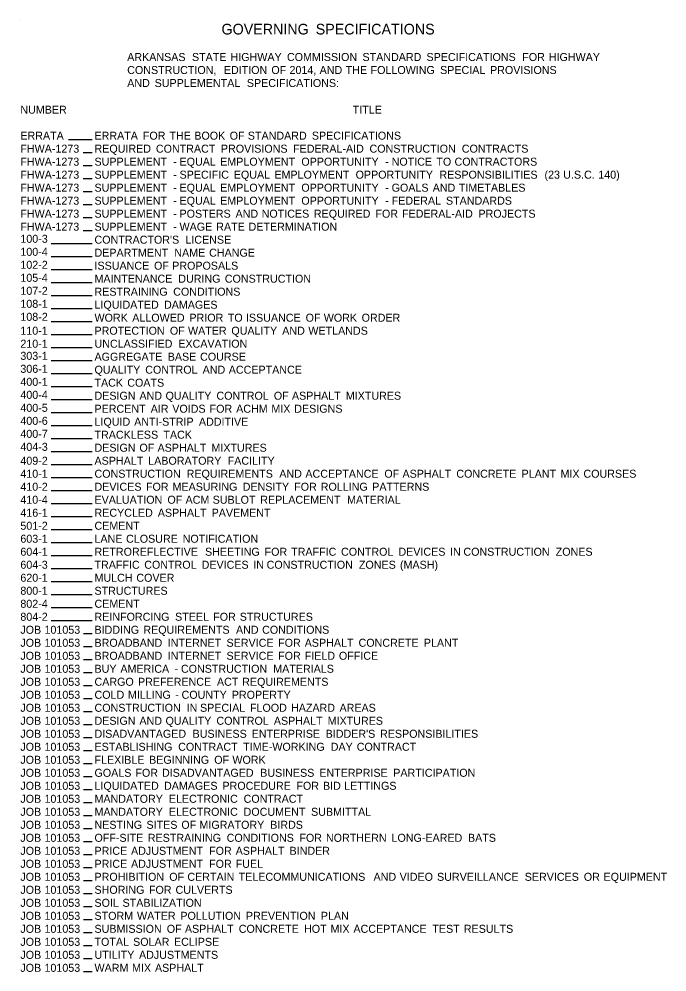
# Model space of a CAD drawing. Extents: x 194 to 1654, y 38 to 1017.
# Drawn here: x 194 to 777, y 126 to 983 of the extents above; entities that cross this region are included whole.
import ezdxf

# ---------------------------------------------------------------- set-up
doc = ezdxf.new("R2010")
doc.units = 0
for name, color, linetype in [('Default', 7, 'Continuous'), ('R_Draft', 7, 'Continuous'), ('R_No Plot', 7, 'Continuous')]:
    doc.layers.add(name, color=color, linetype=linetype)

msp = doc.modelspace()

# ---------------------------------------------------------------- linework, layer by layer
at = {"layer": 'R_Draft'}
for p, q in [((259.88, 874.64), (238.72, 874.64)), ((259.88, 862.94), (251.86, 862.94)), ((259.88, 851.24), (251.86, 851.24)), ((259.88, 839.54), (251.86, 839.54)), ((259.88, 827.84), (251.86, 827.84)), ((259.88, 816.14), (251.86, 816.14)), ((259.88, 804.44), (251.86, 804.44)), ((259.88, 792.74), (251.86, 792.74)), ((259.88, 781.04), (223.07, 781.04)), ((259.88, 769.34), (223.07, 769.34)), ((259.88, 757.64), (223.07, 757.64)), ((259.88, 745.94), (223.07, 745.94)), ((259.88, 734.24), (223.07, 734.24)), ((259.88, 722.54), (223.07, 722.54)), ((259.88, 710.84), (223.07, 710.84)), ((259.88, 699.14), (223.07, 699.14)), ((259.88, 687.44), (223.07, 687.44)), ((259.88, 675.74), (223.07, 675.74)), ((259.88, 664.04), (223.07, 664.04)), ((259.88, 652.34), (223.07, 652.34)), ((259.88, 640.64), (223.07, 640.64)), ((259.88, 628.94), (223.07, 628.94)), ((259.88, 617.24), (223.07, 617.24)), ((259.88, 605.54), (223.07, 605.54)), ((259.88, 593.84), (223.07, 593.84)), ((259.88, 582.14), (223.07, 582.14)), ((259.88, 570.44), (223.07, 570.44)), ((259.88, 558.74), (223.07, 558.74)), ((259.88, 547.04), (223.07, 547.04)), ((259.88, 535.34), (223.07, 535.34)), ((259.88, 523.64), (223.07, 523.64)), ((259.88, 511.94), (223.07, 511.94)), ((259.88, 500.24), (223.07, 500.24)), ((259.88, 488.54), (223.07, 488.54)), ((259.88, 476.84), (223.07, 476.84)), ((259.88, 465.14), (223.07, 465.14)), ((259.88, 453.44), (223.07, 453.44)), ((259.88, 441.74), (223.07, 441.74)), ((259.88, 430.04), (252.22, 430.04)), ((259.88, 418.34), (252.22, 418.34)), ((259.88, 406.64), (252.22, 406.64)), ((259.88, 394.94), (252.22, 394.94)), ((259.88, 383.24), (252.22, 383.24)), ((259.88, 371.54), (252.22, 371.54)), ((259.88, 359.84), (252.22, 359.84)), ((259.88, 348.14), (252.22, 348.14)), ((259.88, 336.44), (252.22, 336.44)), ((259.88, 324.74), (252.22, 324.74)), ((259.88, 313.04), (252.22, 313.04)), ((259.88, 301.34), (252.22, 301.34)), ((259.88, 289.64), (252.22, 289.64)), ((259.88, 277.94), (252.22, 277.94)), ((259.88, 266.24), (252.22, 266.24)), ((259.88, 254.54), (252.22, 254.54)), ((259.88, 242.84), (252.22, 242.84)), ((259.88, 231.14), (252.22, 231.14)), ((259.88, 219.44), (252.22, 219.44)), ((259.88, 207.74), (252.22, 207.74)), ((259.88, 196.04), (252.22, 196.04)), ((259.88, 184.34), (252.22, 184.34)), ((259.88, 172.64), (252.22, 172.64)), ((259.88, 160.94), (252.22, 160.94)), ((259.88, 149.24), (252.22, 149.24)), ((259.88, 137.54), (252.22, 137.54)), ((259.88, 125.84), (252.22, 125.84))]:
    msp.add_line(p, q, dxfattribs=at)
at = {"layer": 'R_No Plot'}
msp.add_line((194.13, 983.18), (194.13, 983.18), dxfattribs=at)

# ---------------------------------------------------------------- texts
at = {"layer": 'Default'}
for s, height, p in [('GOVERNING', 9.6, (376.25, 969.3)), (' SPECIFICATIONS', 9.6, (457.42, 969.3)), ('           ARKANSAS', 7.2, (261.99, 945.42)), (' STATE', 7.2, (346.99, 945.42)), (' HIGHWAY', 7.2, (381.68, 945.42)), (' COMMISSION', 7.2, (432.46, 945.42)), (' STANDARD', 7.2, (500.38, 945.42)), (' SPECIFICATIONS', 7.2, (557.98, 945.42)), (' FOR', 7.2, (644.1, 945.42)), (' HIGHWAY', 7.2, (668, 945.42)), ('           CONSTRUCTION,', 7.2, (261.99, 933.72)), (' EDITION', 7.2, (375.66, 933.72)), (' OF', 7.2, (418.43, 933.72)), (' 2014,', 7.2, (434.74, 933.72)), (' AND', 7.2, (461.8, 933.72)), (' THE', 7.2, (485.3, 933.72)), (' FOLLOWING', 7.2, (507.68, 933.72)), (' SPECIAL', 7.2, (570.2, 933.72)), (' PROVISIONS', 7.2, (615.13, 933.72)), ('           AND', 7.2, (261.99, 922.02)), (' SUPPLEMENTAL', 7.2, (313.42, 922.02)), (' SPECIFICATIONS:', 7.2, (396.37, 922.02)), ('NUMBER', 7.2, (195.3, 898.04)), ('TITLE', 7.2, (494.26, 898.04)), ('ERRATA', 7.2, (195.3, 874.64)), ('ERRATA', 7.2, (261.99, 874.64)), (' FOR', 7.2, (302.82, 874.64)), (' THE', 7.2, (326.71, 874.64)), (' BOOK', 7.2, (349.09, 874.64)), (' OF', 7.2, (380.94, 874.64)), (' STANDARD', 7.2, (397.24, 874.64)), (' SPECIFICATIONS', 7.2, (454.84, 874.64)), ('FHWA-1273', 7.2, (195.3, 862.94)), ('REQUIRED', 7.2, (261.99, 862.94)), (' CONTRACT', 7.2, (314.56, 862.94)), (' PROVISIONS', 7.2, (373.04, 862.94)), (' FEDERAL-AID', 7.2, (437.93, 862.94)), (' CONSTRUCTION', 7.2, (506.7, 862.94)), (' CONTRACTS', 7.2, (589.72, 862.94)), ('FHWA-1273', 7.2, (195.3, 851.24)), ('SUPPLEMENT', 7.2, (261.99, 851.24)), (' EQUAL', 7.2, (335.82, 851.24)), (' EMPLOYMENT', 7.2, (372.37, 851.24)), (' OPPORTUNITY', 7.2, (445.39, 851.24)), (' NOTICE', 7.2, (526.61, 851.24)), (' TO', 7.2, (566.87, 851.24)), (' CONTRACTORS', 7.2, (583.19, 851.24)), (' -', 7.2, (330, 851.24)), (' -', 7.2, (520.78, 851.24)), ('FHWA-1273', 7.2, (195.3, 839.54)), ('SUPPLEMENT', 7.2, (261.99, 839.54)), (' -', 7.2, (330, 839.54)), (' SPECIFIC', 7.2, (335.82, 839.54)), (' EQUAL', 7.2, (384.62, 839.54)), (' EMPLOYMENT', 7.2, (421.16, 839.54)), (' OPPORTUNITY', 7.2, (494.19, 839.54)), (' RESPONSIBILITIES', 7.2, (569.57, 839.54)), (' (23', 7.2, (664.09, 839.54)), (' U.S.C.', 7.2, (680.96, 839.54)), (' 140)', 7.2, (712.5, 839.54)), ('FHWA-1273', 7.2, (195.3, 827.84)), ('SUPPLEMENT', 7.2, (261.99, 827.84)), (' EQUAL', 7.2, (335.82, 827.84)), (' EMPLOYMENT', 7.2, (372.37, 827.84)), (' OPPORTUNITY', 7.2, (445.39, 827.84)), (' GOALS', 7.2, (526.61, 827.84)), (' AND', 7.2, (563.54, 827.84)), (' TIMETABLES', 7.2, (587.04, 827.84)), ('FHWA-1273', 7.2, (195.3, 816.14)), ('SUPPLEMENT', 7.2, (261.99, 816.14)), (' -', 7.2, (330, 827.84)), (' EQUAL', 7.2, (335.82, 816.14)), (' EMPLOYMENT', 7.2, (372.37, 816.14)), (' OPPORTUNITY', 7.2, (445.39, 816.14)), (' -', 7.2, (520.78, 827.84)), (' FEDERAL', 7.2, (526.61, 816.14)), (' STANDARDS', 7.2, (575.45, 816.14)), (' -', 7.2, (330, 816.14)), (' -', 7.2, (520.78, 816.14)), ('FHWA-1273', 7.2, (195.3, 804.44)), ('SUPPLEMENT', 7.2, (261.99, 804.44)), (' -', 7.2, (330, 804.44)), (' POSTERS', 7.2, (335.82, 804.44)), (' AND', 7.2, (386.18, 804.44)), (' NOTICES', 7.2, (409.67, 804.44)), (' REQUIRED', 7.2, (456.66, 804.44)), (' FOR', 7.2, (512.02, 804.44)), (' FEDERAL-AID', 7.2, (535.92, 804.44)), (' PROJECTS', 7.2, (604.69, 804.44)), ('FHWA-1273', 7.2, (195.3, 792.74)), ('SUPPLEMENT', 7.2, (261.99, 792.74)), (' WAGE', 7.2, (335.82, 792.74)), (' RATE', 7.2, (368.82, 792.74)), (' DETERMINATION', 7.2, (397.91, 792.74)), ('100-3', 7.2, (195.3, 781.85)), (' -', 7.2, (330, 792.74)), ("CONTRACTOR'S", 7.2, (261.99, 781.04)), (' LICENSE', 7.2, (341.08, 781.04)), ('100-4', 7.2, (195.3, 770.15)), ('DEPARTMENT', 7.2, (261.99, 769.34)), (' NAME', 7.2, (331.1, 769.34)), (' CHANGE', 7.2, (362.43, 769.34)), ('102-2', 7.2, (195.3, 758.45)), ('ISSUANCE', 7.2, (261.99, 757.64)), (' OF', 7.2, (312.89, 757.64)), (' PROPOSALS', 7.2, (329.2, 757.64)), ('105-4', 7.2, (195.3, 746.75)), ('MAINTENANCE', 7.2, (261.99, 745.94)), (' DURING', 7.2, (334.68, 745.94)), (' CONSTRUCTION', 7.2, (376.53, 745.94)), ('107-2', 7.2, (195.3, 735.05)), ('RESTRAINING', 7.2, (261.99, 734.24)), (' CONDITIONS', 7.2, (330.12, 734.24)), ('108-1', 7.2, (195.3, 723.35)), ('LIQUIDATED', 7.2, (261.99, 722.54)), (' DAMAGES', 7.2, (321.83, 722.54)), ('108-2', 7.2, (195.3, 711.65)), ('WORK', 7.2, (261.99, 710.84)), (' ALLOWED', 7.2, (293.27, 710.84)), (' PRIOR', 7.2, (344.71, 710.84)), (' TO', 7.2, (379.23, 710.84)), (' ISSUANCE', 7.2, (395.55, 710.84)), (' OF', 7.2, (449.24, 710.84)), (' WORK', 7.2, (465.55, 710.84)), (' ORDER', 7.2, (499.61, 710.84)), ('110-1', 7.2, (195.3, 699.14)), ('PROTECTION', 7.2, (261.99, 699.14)), (' OF', 7.2, (327.13, 699.14)), (' WATER', 7.2, (343.43, 699.14)), (' QUALITY', 7.2, (382.42, 699.14)), (' AND', 7.2, (428.18, 699.14)), (' WETLANDS', 7.2, (451.68, 699.14)), ('210-1', 7.2, (195.3, 687.44)), ('UNCLASSIFIED', 7.2, (261.99, 687.44)), (' EXCAVATION', 7.2, (334.69, 687.44)), ('303-1', 7.2, (195.3, 676.55)), ('AGGREGATE', 7.2, (261.99, 675.74)), (' BASE', 7.2, (325.19, 675.74)), (' COURSE', 7.2, (354.29, 675.74)), ('306-1', 7.2, (195.3, 664.85)), ('QUALITY', 7.2, (261.99, 664.04)), (' CONTROL', 7.2, (304.96, 664.04)), (' AND', 7.2, (356.58, 664.04)), (' ACCEPTANCE', 7.2, (380.08, 664.04)), ('400-1', 7.2, (195.3, 653.15)), ('TACK', 7.2, (261.99, 652.34)), (' COATS', 7.2, (288.8, 652.34)), ('400-4', 7.2, (195.3, 641.45)), ('DESIGN', 7.2, (261.99, 640.64)), (' AND', 7.2, (299.74, 640.64)), (' QUALITY', 7.2, (323.24, 640.64)), (' CONTROL', 7.2, (369, 640.64)), (' OF', 7.2, (420.63, 640.64)), (' ASPHALT', 7.2, (436.93, 640.64)), (' MIXTURES', 7.2, (485.37, 640.64)), ('400-5', 7.2, (195.3, 629.75)), ('PERCENT', 7.2, (261.99, 628.94)), (' AIR', 7.2, (309.87, 628.94)), (' VOIDS', 7.2, (329.29, 628.94)), (' FOR', 7.2, (362.87, 628.94)), (' ACHM', 7.2, (386.76, 628.94)), (' MIX', 7.2, (418.42, 628.94)), (' DESIGNS', 7.2, (439.03, 628.94)), ('400-6', 7.2, (195.3, 618.05)), ('LIQUID', 7.2, (261.99, 617.24)), (' ANTI-STRIP', 7.2, (294.99, 617.24)), (' ADDITIVE', 7.2, (353.24, 617.24)), ('400-7', 7.2, (195.3, 606.35)), ('TRACKLESS', 7.2, (261.99, 605.54)), (' TACK', 7.2, (321.29, 605.54)), ('404-3', 7.2, (195.3, 594.65)), ('DESIGN', 7.2, (261.99, 593.84)), (' OF', 7.2, (299.74, 593.84)), (' ASPHALT', 7.2, (316.05, 593.84)), (' MIXTURES', 7.2, (364.49, 593.84)), ('409-2', 7.2, (195.3, 582.14)), ('ASPHALT', 7.2, (261.99, 582.14)), (' LABORATORY', 7.2, (307.64, 582.14)), (' FACILITY', 7.2, (379.12, 582.14)), ('410-1', 7.2, (195.3, 570.44)), ('CONSTRUCTION', 7.2, (261.99, 570.44)), (' REQUIREMENTS', 7.2, (342.21, 570.44)), (' AND', 7.2, (425.53, 570.44)), (' ACCEPTANCE', 7.2, (449.03, 570.44)), (' OF', 7.2, (520.06, 570.44)), (' ASPHALT', 7.2, (536.36, 570.44)), (' CONCRETE', 7.2, (584.8, 570.44)), (' PLANT', 7.2, (643.51, 570.44)), (' MIX', 7.2, (678.53, 570.44)), (' COURSES', 7.2, (699.14, 570.44)), ('410-2', 7.2, (195.3, 558.74)), ('DEVICES', 7.2, (261.99, 558.74)), (' FOR', 7.2, (305.64, 558.74)), (' MEASURING', 7.2, (329.53, 558.74)), (' DENSITY', 7.2, (392.62, 558.74)), (' FOR', 7.2, (438.95, 558.74)), (' ROLLING', 7.2, (462.84, 558.74)), (' PATTERNS', 7.2, (509.16, 558.74)), ('410-4', 7.2, (195.3, 547.04)), ('EVALUATION', 7.2, (261.99, 547.04)), (' OF', 7.2, (324.9, 547.04)), (' ACM', 7.2, (341.21, 547.04)), (' SUBLOT', 7.2, (365.6, 547.04)), (' REPLACEMENT', 7.2, (408.44, 547.04)), (' MATERIAL', 7.2, (486.51, 547.04)), ('416-1', 7.2, (195.3, 535.34)), ('RECYCLED', 7.2, (261.99, 535.34)), (' ASPHALT', 7.2, (316.24, 535.34)), (' PAVEMENT', 7.2, (364.68, 535.34)), ('501-2', 7.2, (195.3, 523.64)), ('CEMENT', 7.2, (261.99, 523.64)), ('603-1', 7.2, (195.3, 511.94)), ('LANE', 7.2, (261.99, 511.94)), (' CLOSURE', 7.2, (287.73, 511.94)), (' NOTIFICATION', 7.2, (338.63, 511.94)), ('604-1', 7.2, (195.3, 500.24)), ('RETROREFLECTIVE', 7.2, (261.99, 500.24)), (' SHEETING', 7.2, (358.73, 500.24)), (' FOR', 7.2, (412.32, 500.24)), (' TRAFFIC', 7.2, (436.21, 500.24)), (' CONTROL', 7.2, (481.08, 500.24)), (' DEVICES', 7.2, (532.7, 500.24)), (' IN', 7.2, (579.14, 500.24)), (' CONSTRUCTION', 7.2, (591.17, 500.24)), (' ZONES', 7.2, (674.19, 500.24)), ('604-3', 7.2, (195.3, 488.54)), ('TRAFFIC', 7.2, (261.99, 488.54)), (' CONTROL', 7.2, (304.07, 488.54)), (' DEVICES', 7.2, (355.69, 488.54)), (' IN', 7.2, (402.13, 488.54)), (' CONSTRUCTION', 7.2, (414.16, 488.54)), (' ZONES', 7.2, (497.17, 488.54)), (' (MASH)', 7.2, (534.1, 488.54)), ('620-1', 7.2, (195.3, 476.84)), ('MULCH', 7.2, (261.99, 476.84)), (' COVER', 7.2, (296.95, 476.84)), ('800-1', 7.2, (195.3, 465.14)), ('STRUCTURES', 7.2, (261.99, 465.14)), ('802-4', 7.2, (195.3, 453.44)), ('CEMENT', 7.2, (261.99, 453.44)), ('804-2', 7.2, (195.3, 441.74)), ('REINFORCING', 7.2, (261.99, 441.74)), (' STEEL', 7.2, (331.79, 441.74)), (' FOR', 7.2, (366.1, 441.74)), (' STRUCTURES', 7.2, (389.99, 441.74)), ('JOB', 7.2, (195.3, 430.04)), (' 101053', 7.2, (214.33, 430.04)), ('BIDDING', 7.2, (261.99, 430.04)), (' REQUIREMENTS', 7.2, (303.28, 430.04)), (' CONDITIONS', 7.2, (410.1, 430.04)), (' AND', 7.2, (386.6, 430.04)), ('JOB', 7.2, (195.3, 418.34)), (' 101053', 7.2, (214.33, 418.34)), ('BROADBAND', 7.2, (261.99, 418.34)), (' INTERNET', 7.2, (325.19, 418.34)), (' SERVICE', 7.2, (378.09, 418.34)), (' FOR', 7.2, (424.51, 418.34)), (' ASPHALT', 7.2, (448.41, 418.34)), (' CONCRETE', 7.2, (496.85, 418.34)), (' PLANT', 7.2, (555.56, 418.34)), ('JOB', 7.2, (195.3, 406.64)), (' 101053', 7.2, (214.33, 406.64)), ('BROADBAND', 7.2, (261.99, 406.64)), (' INTERNET', 7.2, (325.19, 406.64)), (' SERVICE', 7.2, (378.09, 406.64)), (' FOR', 7.2, (424.51, 406.64)), (' FIELD', 7.2, (448.41, 406.64)), (' OFFICE', 7.2, (479.17, 406.64)), ('JOB', 7.2, (195.3, 394.94)), (' 101053', 7.2, (214.33, 394.94)), ('BUY', 7.2, (261.99, 394.94)), (' AMERICA', 7.2, (282.6, 394.94)), (' -', 7.2, (331.25, 394.94)), (' CONSTRUCTION', 7.2, (337.08, 394.94)), (' MATERIALS', 7.2, (420.1, 394.94)), ('JOB', 7.2, (195.3, 383.24)), (' 101053', 7.2, (214.33, 383.24)), ('CARGO', 7.2, (261.99, 383.24)), (' PREFERENCE', 7.2, (298.44, 383.24)), (' ACT', 7.2, (369.46, 383.24)), (' REQUIREMENTS', 7.2, (392.17, 383.24)), ('JOB', 7.2, (195.3, 371.54)), (' 101053', 7.2, (214.33, 371.54)), ('COLD', 7.2, (261.99, 371.54)), (' MILLING', 7.2, (289.4, 371.54)), (' COUNTY', 7.2, (337.64, 371.54)), (' PROPERTY', 7.2, (382.83, 371.54)), (' -', 7.2, (331.81, 371.54)), ('JOB', 7.2, (195.3, 359.84)), (' 101053', 7.2, (214.33, 359.84)), ('CONSTRUCTION', 7.2, (261.99, 359.84)), (' IN', 7.2, (342.21, 359.84)), (' SPECIAL', 7.2, (354.24, 359.84)), (' FLOOD', 7.2, (399.18, 359.84)), (' HAZARD', 7.2, (436.09, 359.84)), (' AREAS', 7.2, (479.71, 359.84)), ('JOB', 7.2, (195.3, 348.14)), (' 101053', 7.2, (214.33, 348.14)), ('DESIGN', 7.2, (261.99, 348.14)), (' AND', 7.2, (299.74, 348.14)), (' QUALITY', 7.2, (323.24, 348.14)), (' CONTROL', 7.2, (369, 348.14)), (' ASPHALT', 7.2, (420.63, 348.14)), (' MIXTURES', 7.2, (469.07, 348.14)), ('JOB', 7.2, (195.3, 336.44)), (' 101053', 7.2, (214.33, 336.44)), ('DISADVANTAGED', 7.2, (261.99, 336.44)), (' BUSINESS', 7.2, (347.55, 336.44)), (' ENTERPRISE', 7.2, (400.7, 336.44)), (" BIDDER'S", 7.2, (467.25, 336.44)), (' RESPONSIBILITIES', 7.2, (516.16, 336.44)), ('JOB', 7.2, (195.3, 324.74)), (' 101053', 7.2, (214.33, 324.74)), ('ESTABLISHING', 7.2, (261.99, 324.74)), (' CONTRACT', 7.2, (334.6, 324.74)), (' TIME-WORKING', 7.2, (393.08, 324.74)), (' DAY', 7.2, (471.81, 324.74)), (' CONTRACT', 7.2, (495.21, 324.74)), ('JOB', 7.2, (195.3, 313.04)), (' 101053', 7.2, (214.33, 313.04)), ('FLEXIBLE', 7.2, (261.99, 313.04)), (' BEGINNING', 7.2, (308.42, 313.04)), (' OF', 7.2, (367.04, 313.04)), (' WORK', 7.2, (383.35, 313.04)), ('JOB', 7.2, (195.3, 301.34)), (' 101053', 7.2, (214.33, 301.34)), ('GOALS', 7.2, (261.99, 301.34)), (' FOR', 7.2, (296.13, 301.34)), (' DISADVANTAGED', 7.2, (320.03, 301.34)), (' BUSINESS', 7.2, (408.38, 301.34)), (' ENTERPRISE', 7.2, (461.53, 301.34)), (' PARTICIPATION', 7.2, (528.08, 301.34)), ('JOB', 7.2, (195.3, 289.64)), (' 101053', 7.2, (214.33, 289.64)), ('LIQUIDATED', 7.2, (261.99, 289.64)), (' DAMAGES', 7.2, (321.83, 289.64)), (' PROCEDURE', 7.2, (374.41, 289.64)), (' FOR', 7.2, (440.95, 289.64)), (' BID', 7.2, (464.85, 289.64)), (' LETTINGS', 7.2, (483.87, 289.64)), ('JOB', 7.2, (195.3, 277.94)), (' 101053', 7.2, (214.33, 277.94)), ('MANDATORY', 7.2, (261.99, 277.94)), (' ELECTRONIC', 7.2, (326.2, 277.94)), (' CONTRACT', 7.2, (393.44, 277.94)), ('JOB', 7.2, (195.3, 266.24)), (' 101053', 7.2, (214.33, 266.24)), ('MANDATORY', 7.2, (261.99, 266.24)), (' ELECTRONIC', 7.2, (326.2, 266.24)), (' DOCUMENT', 7.2, (393.44, 266.24)), (' SUBMITTAL', 7.2, (454.15, 266.24)), ('JOB', 7.2, (195.3, 254.54)), (' 101053', 7.2, (214.33, 254.54)), ('NESTING', 7.2, (261.99, 254.54)), (' SITES', 7.2, (306.08, 254.54)), (' OF', 7.2, (337.42, 254.54)), (' MIGRATORY', 7.2, (353.73, 254.54)), (' BIRDS', 7.2, (417.37, 254.54)), ('JOB', 7.2, (195.3, 242.84)), (' 101053', 7.2, (214.33, 242.84)), ('OFF-SITE', 7.2, (261.99, 242.84)), (' RESTRAINING', 7.2, (307.28, 242.84)), (' CONDITIONS', 7.2, (378.2, 242.84)), (' FOR', 7.2, (443.63, 242.84)), (' NORTHERN', 7.2, (467.52, 242.84)), (' LONG-EARED', 7.2, (526.5, 242.84)), (' BATS', 7.2, (595.28, 242.84)), ('JOB', 7.2, (195.3, 231.14)), (' 101053', 7.2, (214.33, 231.14)), ('PRICE', 7.2, (261.99, 231.14)), (' ADJUSTMENT', 7.2, (292.2, 231.14)), (' FOR', 7.2, (362.43, 231.14)), (' ASPHALT', 7.2, (386.32, 231.14)), (' BINDER', 7.2, (434.76, 231.14)), ('JOB', 7.2, (195.3, 219.44)), (' 101053', 7.2, (214.33, 219.44)), ('PRICE', 7.2, (261.99, 219.44)), (' ADJUSTMENT', 7.2, (292.2, 219.44)), (' FOR', 7.2, (362.43, 219.44)), (' FUEL', 7.2, (386.32, 219.44)), ('JOB', 7.2, (195.3, 207.74)), (' 101053', 7.2, (214.33, 207.74)), ('PROHIBITION', 7.2, (261.99, 207.74)), (' OF', 7.2, (326.57, 207.74)), (' CERTAIN', 7.2, (342.87, 207.74)), (' TELECOMMUNICATIONS', 7.2, (389, 207.74)), (' AND', 7.2, (510.33, 207.74)), (' VIDEO', 7.2, (533.82, 207.74)), (' SURVEILLANCE', 7.2, (567.48, 207.74)), (' SERVICES', 7.2, (646.33, 207.74)), (' OR', 7.2, (699.48, 207.74)), (' EQUIPMENT', 7.2, (717.23, 207.74)), ('JOB', 7.2, (195.3, 196.04)), (' 101053', 7.2, (214.33, 196.04)), ('SHORING', 7.2, (261.99, 196.04)), (' FOR', 7.2, (308.31, 196.04)), (' CULVERTS', 7.2, (332.21, 196.04)), ('JOB', 7.2, (195.3, 184.34)), (' 101053', 7.2, (214.33, 184.34)), ('SOIL', 7.2, (261.99, 184.34)), (' STABILIZATION', 7.2, (284.56, 184.34)), ('JOB', 7.2, (195.3, 172.64)), (' 101053', 7.2, (214.33, 172.64)), ('STORM', 7.2, (261.99, 172.64)), (' WATER', 7.2, (297.56, 172.64)), (' POLLUTION', 7.2, (336.55, 172.64)), (' PREVENTION', 7.2, (395.54, 172.64)), (' PLAN', 7.2, (462.92, 172.64)), ('JOB', 7.2, (195.3, 160.94)), (' 101053', 7.2, (214.33, 160.94)), ('SUBMISSION', 7.2, (261.99, 160.94)), (' OF', 7.2, (324.34, 160.94)), (' ASPHALT', 7.2, (340.64, 160.94)), (' CONCRETE', 7.2, (389.08, 160.94)), (' HOT', 7.2, (447.8, 160.94)), (' MIX', 7.2, (471.63, 160.94)), (' ACCEPTANCE', 7.2, (492.24, 160.94)), (' TEST', 7.2, (563.26, 160.94)), (' RESULTS', 7.2, (591.57, 160.94)), ('JOB', 7.2, (195.3, 149.24)), (' 101053', 7.2, (214.33, 149.24)), ('TOTAL', 7.2, (261.99, 149.24)), (' SOLAR', 7.2, (294.06, 149.24)), (' ECLIPSE', 7.2, (330.82, 149.24)), ('JOB', 7.2, (195.3, 137.54)), (' 101053', 7.2, (214.33, 137.54)), ('UTILITY', 7.2, (261.99, 137.54)), (' ADJUSTMENTS', 7.2, (299.36, 137.54)), ('JOB', 7.2, (195.3, 125.84)), (' 101053', 7.2, (214.33, 125.84)), ('WARM', 7.2, (261.99, 125.84)), (' MIX', 7.2, (293.09, 125.84)), (' ASPHALT', 7.2, (313.7, 125.84))]:
    msp.add_text(s, height=height, dxfattribs=at).set_placement(p)

doc.saveas('drawing.dxf')
